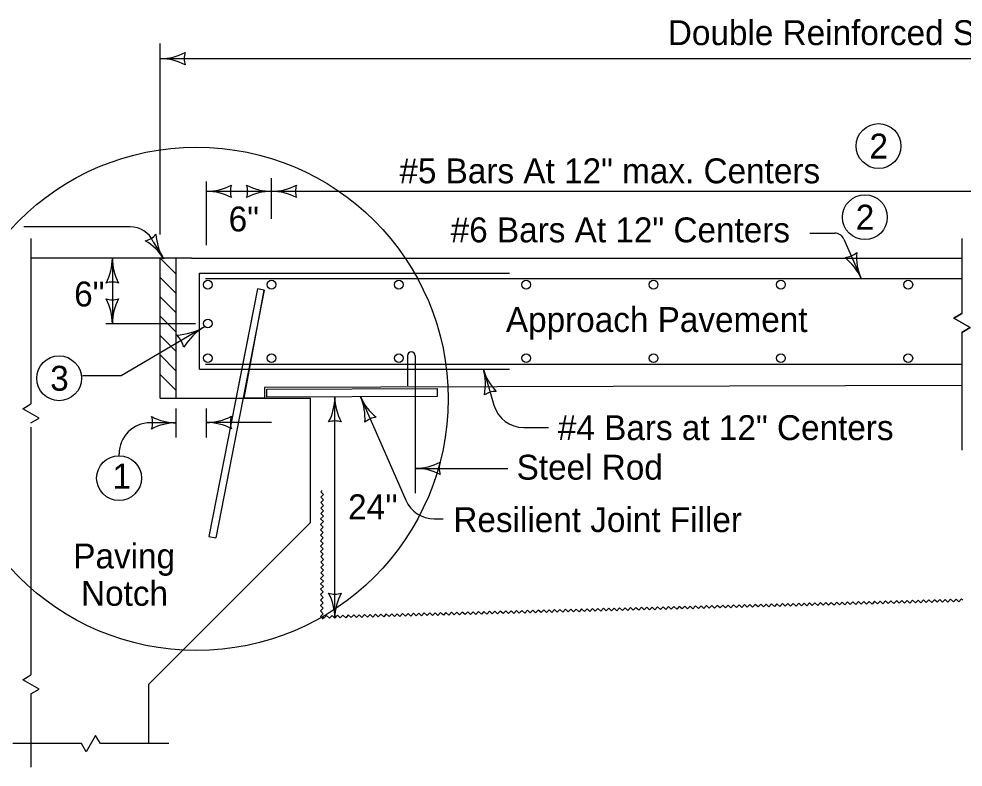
# Model space of a CAD drawing. Extents: x 8925 to 81668, y 4369 to 11918.
# Drawn here: x 10439 to 11198, y 11317 to 11918 of the extents above; entities that cross this region are included whole.
import ezdxf

# ---------------------------------------------------------------- set-up
doc = ezdxf.new("R2010")
doc.units = 0
for name, color, linetype in [('dsnShtPlotShapeBatchPrint', 7, 'Continuous'), ('dsnStdBorder', 7, 'Continuous'), ('Level 2', 7, 'Continuous'), ('Level 3', 7, 'Continuous')]:
    doc.layers.add(name, color=color, linetype=linetype)

msp = doc.modelspace()

# ---------------------------------------------------------------- linework, layer by layer
at = {"layer": 'dsnShtPlotShapeBatchPrint'}
for p, q in [((10552.7, 11779.04), (10552.7, 11897.97)), ((10552.7, 11885.92), (11924.35, 11885.92)), ((10642.06, 11757.38), (10642.06, 11789.95)), ((10589.84, 11736.03), (10589.84, 11787.22)), ((10552.7, 11744.67), (10552.7, 11779.04)), ((10642.06, 11779.35), (10589.84, 11779.35)), ((11212.31, 11779.35), (10642.06, 11779.35)), ((10528.55, 11750.92), (10443.13, 11750.92)), ((11074.65, 11745.77), (11094.51, 11745.77)), ((11101.92, 11740.93), (11115.71, 11709.42)), ((10514.2, 11725.71), (10514.2, 11673.05)), ((10565.57, 11613.18), (10565.57, 11725.71)), ((10565.57, 11613.18), (10565.57, 11725.71)), ((10577.7, 11725.71), (11196.67, 11725.71)), ((11196.67, 11725.71), (11196.67, 11681.27)), ((10630.73, 11701.11), (10591.71, 11502.08)), ((10636.29, 11700.02), (10597.26, 11500.99)), ((10630.73, 11701.11), (10613.41, 11612.76)), ((10620.09, 11613.18), (10636.29, 11700.02)), ((10636.29, 11700.02), (10630.73, 11701.11)), ((10636.29, 11700.02), (10630.73, 11701.11)), ((11196.67, 11681.27), (11190.1, 11677.49)), ((11190.1, 11677.49), (11203.23, 11669.89)), ((10581.11, 11673.05), (10509, 11673.05)), ((10588.33, 11670.58), (10521.42, 11631.21)), ((11203.23, 11669.89), (11196.67, 11666.11)), ((11196.67, 11666.11), (11196.67, 11623.41)), ((10812.25, 11636.46), (10820.69, 11607.62)), ((10521.42, 11631.21), (10490.23, 11631.21)), ((11196.67, 11623.41), (10636.5, 11621.92)), ((10636.5, 11621.92), (10636.5, 11613.18)), ((10636.5, 11621.91), (10636.5, 11613.18)), ((10638.22, 11620.45), (10775.14, 11620.96)), ((10775.14, 11620.96), (10775.16, 11614.48)), ((10613.41, 11612.76), (10565.57, 11613.18)), ((10636.5, 11613.18), (10620.09, 11613.18)), ((10638.25, 11613.98), (10638.22, 11620.45)), ((10775.16, 11614.48), (10638.25, 11613.98)), ((10692.98, 11436.67), (10692.98, 11614.18)), ((10713.64, 11614.25), (10749.94, 11531.33)), ((10565.57, 11581.77), (10565.57, 11605.08)), ((10589.84, 11581.62), (10589.84, 11604.93)), ((10565.77, 11593.49), (10544.6, 11593.49)), ((10642.06, 11593.76), (10589.84, 11593.76)), ((10844.68, 11589.65), (10864.46, 11589.65)), ((10519.6, 11567.08), (10519.6, 11568.49)), ((10757.52, 11556.9), (10831.85, 11556.9)), ((10772.84, 11516.36), (10780.05, 11516.36)), ((10591.71, 11502.08), (10597.26, 11500.99))]:
    msp.add_line(p, q, dxfattribs=at)
for points in [[(11196.67, 11681.27), (11190.1, 11677.49), (11203.24, 11669.89), (11196.67, 11666.11)], [(10682.7, 11539.17), (10681.61, 11538.09), (10683.78, 11535.9), (10681.59, 11533.72), (10683.77, 11531.54), (10681.58, 11529.36), (10683.75, 11527.18), (10681.56, 11525.01), (10683.74, 11522.82), (10681.56, 11520.64), (10683.72, 11518.46), (10681.54, 11516.28), (10683.7, 11514.1), (10681.52, 11511.93), (10683.69, 11509.74), (10681.51, 11507.56), (10683.68, 11505.38), (10681.49, 11503.2), (10683.66, 11501.01), (10681.48, 11498.84), (10683.65, 11496.66), (10681.47, 11494.48), (10683.63, 11492.29), (10681.45, 11490.12), (10683.62, 11487.94), (10682.53, 11486.85)], [(10682.7, 11487.1), (10681.61, 11486.02), (10683.78, 11483.83), (10681.59, 11481.66), (10683.77, 11479.47), (10681.58, 11477.29), (10683.75, 11475.11), (10681.56, 11472.94), (10683.74, 11470.75), (10681.55, 11468.57), (10683.72, 11466.39), (10681.54, 11464.22), (10683.7, 11462.03), (10681.52, 11459.86), (10683.69, 11457.67), (10681.5, 11455.49), (10683.68, 11453.31), (10681.49, 11451.13), (10683.66, 11448.95), (10681.48, 11446.77), (10683.65, 11444.59), (10681.47, 11442.41), (10683.63, 11440.22), (10681.45, 11438.05), (10683.62, 11435.87)], [(10988.23, 11445.5), (10987.11, 11446.56), (10984.98, 11444.33), (10982.75, 11446.45), (10980.63, 11444.21), (10978.39, 11446.33), (10976.27, 11444.1), (10974.03, 11446.22), (10971.91, 11443.99), (10969.67, 11446.11), (10967.55, 11443.88), (10965.31, 11445.99), (10963.19, 11443.76), (10960.96, 11445.88), (10958.83, 11443.64), (10956.6, 11445.77), (10954.47, 11443.53), (10952.23, 11445.65), (10950.11, 11443.42), (10947.87, 11445.54), (10945.75, 11443.3), (10943.52, 11445.42), (10941.4, 11443.19), (10939.16, 11445.31), (10937.04, 11443.08), (10935.92, 11444.14)], [(11040.53, 11446.87), (11039.41, 11447.93), (11037.29, 11445.69), (11035.06, 11447.81), (11032.94, 11445.58), (11030.7, 11447.7), (11028.57, 11445.47), (11026.34, 11447.59), (11024.21, 11445.35), (11021.97, 11447.47), (11019.85, 11445.24), (11017.62, 11447.36), (11015.5, 11445.13), (11013.26, 11447.25), (11011.14, 11445.01), (11008.9, 11447.13), (11006.78, 11444.9), (11004.54, 11447.02), (11002.42, 11444.78), (11000.18, 11446.9), (10998.06, 11444.67), (10995.82, 11446.79), (10993.7, 11444.55), (10991.47, 11446.68), (10989.34, 11444.44), (10988.23, 11445.5)], [(11092.84, 11448.24), (11091.72, 11449.29), (11089.6, 11447.06), (11087.36, 11449.18), (11085.24, 11446.95), (11083, 11449.06), (11080.88, 11446.83), (11078.64, 11448.95), (11076.52, 11446.72), (11074.28, 11448.84), (11072.16, 11446.61), (11069.92, 11448.73), (11067.81, 11446.49), (11065.57, 11448.61), (11063.44, 11446.38), (11061.21, 11448.5), (11059.09, 11446.27), (11056.85, 11448.39), (11054.72, 11446.15), (11052.49, 11448.27), (11050.37, 11446.03), (11048.13, 11448.15), (11046.01, 11445.92), (11043.77, 11448.04), (11041.65, 11445.81), (11040.53, 11446.87)], [(11145.15, 11449.6), (11144.03, 11450.66), (11141.91, 11448.43), (11139.67, 11450.54), (11137.55, 11448.31), (11135.31, 11450.43), (11133.18, 11448.2), (11130.95, 11450.32), (11128.83, 11448.09), (11126.59, 11450.2), (11124.47, 11447.97), (11122.23, 11450.09), (11120.11, 11447.86), (11117.87, 11449.98), (11115.75, 11447.75), (11113.51, 11449.87), (11111.39, 11447.63), (11109.16, 11449.75), (11107.04, 11447.52), (11104.8, 11449.64), (11102.67, 11447.4), (11100.44, 11449.52), (11098.31, 11447.29), (11096.08, 11449.41), (11093.96, 11447.17), (11092.84, 11448.24)], [(11197.45, 11450.97), (11196.34, 11452.02), (11194.21, 11449.79), (11191.98, 11451.91), (11189.85, 11449.68), (11187.61, 11451.8), (11185.49, 11449.57), (11183.26, 11451.68), (11181.14, 11449.45), (11178.9, 11451.57), (11176.77, 11449.34), (11174.54, 11451.46), (11172.42, 11449.23), (11170.18, 11451.34), (11168.06, 11449.11), (11165.82, 11451.23), (11163.7, 11449), (11161.46, 11451.11), (11159.34, 11448.89), (11157.1, 11451), (11154.98, 11448.77), (11152.75, 11450.89), (11150.62, 11448.65), (11148.38, 11450.77), (11146.26, 11448.54), (11145.15, 11449.6)], [(10726.7, 11438.67), (10725.58, 11439.73), (10723.45, 11437.5), (10721.22, 11439.62), (10719.09, 11437.38), (10716.86, 11439.5), (10714.74, 11437.27), (10712.5, 11439.39), (10710.38, 11437.16), (10708.14, 11439.28), (10706.02, 11437.04), (10703.78, 11439.16), (10701.66, 11436.93), (10699.42, 11439.05), (10697.3, 11436.82), (10695.06, 11438.94), (10692.94, 11436.7), (10690.71, 11438.82), (10688.58, 11436.59), (10686.34, 11438.71), (10684.22, 11436.48), (10683.16, 11437.48)], [(10779, 11440.04), (10777.88, 11441.1), (10775.76, 11438.86), (10773.52, 11440.98), (10771.4, 11438.75), (10769.16, 11440.87), (10767.04, 11438.64), (10764.81, 11440.76), (10762.68, 11438.52), (10760.45, 11440.64), (10758.32, 11438.41), (10756.09, 11440.53), (10753.97, 11438.3), (10751.73, 11440.42), (10749.61, 11438.18), (10747.37, 11440.3), (10745.25, 11438.07), (10743.01, 11440.19), (10740.89, 11437.95), (10738.65, 11440.08), (10736.53, 11437.84), (10734.3, 11439.96), (10732.17, 11437.72), (10729.93, 11439.85), (10727.81, 11437.61), (10726.7, 11438.67)], [(10831.31, 11441.41), (10830.19, 11442.46), (10828.07, 11440.23), (10825.83, 11442.35), (10823.71, 11440.12), (10821.47, 11442.23), (10819.35, 11440), (10817.11, 11442.12), (10814.99, 11439.89), (10812.75, 11442.01), (10810.63, 11439.78), (10808.4, 11441.89), (10806.27, 11439.66), (10804.04, 11441.78), (10801.91, 11439.55), (10799.67, 11441.67), (10797.56, 11439.43), (10795.32, 11441.55), (10793.19, 11439.32), (10790.96, 11441.44), (10788.83, 11439.21), (10786.6, 11441.33), (10784.48, 11439.09), (10782.24, 11441.21), (10780.12, 11438.98), (10779, 11440.04)], [(10883.62, 11442.77), (10882.5, 11443.83), (10880.37, 11441.6), (10878.14, 11443.71), (10876.01, 11441.48), (10873.77, 11443.6), (10871.66, 11441.37), (10869.42, 11443.49), (10867.29, 11441.26), (10865.06, 11443.37), (10862.93, 11441.14), (10860.7, 11443.26), (10858.58, 11441.03), (10856.35, 11443.15), (10854.22, 11440.92), (10851.98, 11443.03), (10849.86, 11440.8), (10847.62, 11442.92), (10845.5, 11440.69), (10843.26, 11442.8), (10841.14, 11440.57), (10838.91, 11442.69), (10836.79, 11440.46), (10834.55, 11442.58), (10832.43, 11440.34), (10831.31, 11441.41)], [(10935.92, 11444.14), (10934.8, 11445.19), (10932.68, 11442.96), (10930.45, 11445.08), (10928.32, 11442.85), (10926.08, 11444.97), (10923.96, 11442.74), (10921.72, 11444.85), (10919.6, 11442.62), (10917.36, 11444.74), (10915.24, 11442.51), (10913.01, 11444.63), (10910.88, 11442.4), (10908.65, 11444.51), (10906.53, 11442.28), (10904.29, 11444.4), (10902.17, 11442.17), (10899.93, 11444.29), (10897.81, 11442.05), (10895.57, 11444.17), (10893.45, 11441.94), (10891.21, 11444.06), (10889.09, 11441.82), (10886.85, 11443.94), (10884.73, 11441.71), (10883.62, 11442.77)]]:
    msp.add_lwpolyline(points, dxfattribs=at)
for centre, radius in [((10581.86, 11612.73), 202.08), ((10590.91, 11673.22), 3.55)]:
    msp.add_circle(centre, radius, dxfattribs=at)
for centre, radius in [((10528.55, 11730.72), 20.21), ((11094.51, 11737.69), 8.08)]:
    msp.add_arc(centre, radius, 23.64012, 90, dxfattribs=at)
at = {"layer": 'dsnStdBorder'}
for p, q in [((10448.81, 11741.35), (10448.81, 11702.2)), ((10547.06, 11738.82), (10555.39, 11725.19)), ((11196.67, 11741.35), (11196.67, 11681.27)), ((10577.7, 11725.71), (10448.81, 11725.71)), ((10552.7, 11613.18), (10552.7, 11725.71)), ((10565.57, 11712.84), (10552.7, 11725.71)), ((10577.7, 11725.71), (11196.67, 11725.71)), ((10584.28, 11713.62), (10833.14, 11713.62)), ((10584.28, 11636.46), (10584.28, 11713.62)), ((10565.57, 11697.29), (10552.7, 11710.16)), ((10588.91, 11709.42), (11196.67, 11709.42)), ((10448.81, 11702.2), (10448.81, 11608.61)), ((10565.57, 11681.73), (10552.7, 11694.6)), ((10565.57, 11666.17), (10552.7, 11679.04)), ((10565.57, 11650.62), (10552.7, 11663.49)), ((11196.67, 11666.11), (11196.67, 11571.49)), ((10565.57, 11635.06), (10552.7, 11647.93)), ((10584.28, 11636.46), (10833.14, 11636.46)), ((10588.91, 11640.46), (11196.67, 11640.46)), ((10565.57, 11619.51), (10552.7, 11632.38)), ((11196.67, 11623.41), (10636.5, 11621.92)), ((10638.22, 11620.45), (10775.14, 11620.96)), ((10775.14, 11620.96), (10775.16, 11614.48)), ((10552.7, 11613.18), (10673.43, 11613.18)), ((10638.25, 11613.98), (10638.22, 11620.45)), ((10775.16, 11614.48), (10638.25, 11613.98)), ((10673.43, 11513.56), (10673.43, 11613.18)), ((10448.81, 11590.07), (10448.81, 11390.98)), ((10543.59, 11383.73), (10673.43, 11513.56)), ((10543.59, 11335.88), (10543.59, 11383.73)), ((10448.81, 11375.82), (10448.81, 11317.01)), ((10489.43, 11335.88), (10434.36, 11335.88)), ((10559.65, 11335.88), (10504.59, 11335.88))]:
    msp.add_line(p, q, dxfattribs=at)
for points in [[(11196.67, 11666.11), (11203.24, 11669.89), (11190.1, 11677.49), (11196.67, 11681.27)], [(10448.81, 11593.45), (10455.37, 11597.23), (10442.24, 11604.82), (10448.81, 11608.6)], [(10448.81, 11375.82), (10455.37, 11379.6), (10442.24, 11387.2), (10448.81, 11390.98)], [(10504.59, 11335.87), (10500.8, 11342.44), (10493.21, 11329.31), (10489.43, 11335.87)]]:
    msp.add_lwpolyline(points, dxfattribs=at)
for centre, radius in [((11129.74, 11815.71), 18), ((11118.75, 11758.59), 18), ((10590.91, 11704.42), 3.55), ((10642.06, 11704.42), 3.55), ((10744.37, 11704.42), 3.55), ((10846.67, 11704.42), 3.55), ((10948.98, 11704.42), 3.55), ((11051.28, 11704.42), 3.55), ((11153.59, 11704.42), 3.55), ((10471.42, 11629.24), 18), ((10590.91, 11645.36), 3.55), ((10642.06, 11645.36), 3.55), ((10744.37, 11645.36), 3.55), ((10846.67, 11645.36), 3.55), ((10948.98, 11645.36), 3.55), ((11051.28, 11645.36), 3.55), ((11153.59, 11645.36), 3.55), ((10519.6, 11549.08), 18)]:
    msp.add_circle(centre, radius, dxfattribs=at)
for centre, radius, start, end in [((11101.04, 11742.93), 16.85, 275.90677, 311.37347), ((11155.68, 11726.91), 43.63, 175.56763, 203.64012), ((11075.74, 11691.92), 43.63, 23.64012, 51.71261), ((10563.78, 11712.28), 48.39, 272.40408, 300.47657), ((10612.87, 11628.88), 48.39, 120.47657, 148.54906), ((10553.36, 11650), 18.69, 12.74322, 48.20992), ((10844.68, 11614.65), 25, 196.32643, 270), ((10544.6, 11568.49), 25, 90, 180), ((10772.84, 11541.36), 25, 203.64012, 270), ((10692.98, 11472.3), 16.42, 252.26665, 287.73335), ((10650.48, 11436.67), 42.5, 360, 28.07249), ((10735.48, 11436.67), 42.5, 151.92751, 180)]:
    msp.add_arc(centre, radius, start, end, dxfattribs=at)
at = {"layer": 'Level 2'}
for p, q in [((10751.23, 11647.3), (10751.23, 11623.15)), ((10757.52, 11647.3), (10757.52, 11537.08))]:
    msp.add_line(p, q, dxfattribs=at)
msp.add_arc((10754.37, 11647.3), 3.15, 0, 180, dxfattribs=at)
at = {"layer": 'Level 3'}
for centre, radius, start, end in [((10552.7, 11928.42), 42.5, 270, 298.07249), ((10588.34, 11885.92), 16.42, 162.26665, 197.73335), ((10552.7, 11843.42), 42.5, 61.92751, 90), ((10589.84, 11821.85), 42.5, 270, 298.07249), ((10625.48, 11779.35), 16.42, 162.26665, 197.73335), ((10606.43, 11779.35), 16.42, 342.26665, 17.73335), ((10642.06, 11821.85), 42.5, 241.92751, 270), ((10642.06, 11821.85), 42.5, 270, 298.07249), ((10677.7, 11779.35), 16.42, 162.26665, 197.73335), ((10589.84, 11736.85), 42.5, 61.92751, 90), ((10642.06, 11736.85), 42.5, 90, 118.07249), ((10642.06, 11736.85), 42.5, 61.92751, 90), ((10536.8, 11755.6), 16.42, 283.71154, 319.17824), ((10591.65, 11747.37), 42.5, 183.3724, 211.44489), ((10519.13, 11703.02), 42.5, 31.44489, 59.51738), ((10471.7, 11725.71), 42.5, 331.92751, 360), ((10556.7, 11725.71), 42.5, 180, 208.07249), ((10514.2, 11690.08), 16.42, 72.26665, 107.73335), ((10514.2, 11708.69), 16.42, 252.26665, 287.73335), ((10471.7, 11673.05), 42.5, 360, 28.07249), ((10556.7, 11673.05), 42.5, 151.92751, 180), ((10853.03, 11648.4), 42.5, 196.32643, 224.39892), ((10771.46, 11624.51), 42.5, 348.25394, 16.32643), ((10650.48, 11614.18), 42.5, 331.92751, 360), ((10735.48, 11614.18), 42.5, 180, 208.07249), ((10752.58, 11631.29), 42.5, 203.64012, 231.71261), ((10674.71, 11597.21), 42.5, 355.56763, 23.64012), ((10822.26, 11602.26), 16.42, 88.59307, 124.05978), ((10530.13, 11593.49), 16.42, 342.26665, 17.73335), ((10565.77, 11635.99), 42.5, 241.92751, 270), ((10589.84, 11636.26), 42.5, 270, 298.07249), ((10625.48, 11593.76), 16.42, 162.26665, 197.73335), ((10565.77, 11550.99), 42.5, 90, 118.07249), ((10589.84, 11551.26), 42.5, 61.92751, 90), ((10692.98, 11578.54), 16.42, 72.26665, 107.73335), ((10727.93, 11581.61), 16.42, 95.90677, 131.37347), ((10757.52, 11599.4), 42.5, 270, 298.07249), ((10793.16, 11556.9), 16.42, 162.26665, 197.73335), ((10757.52, 11514.4), 42.5, 61.92751, 90)]:
    msp.add_arc(centre, radius, start, end, dxfattribs=at)

# ---------------------------------------------------------------- texts
at = {"layer": 'dsnShtPlotShapeBatchPrint'}
for s, p in [('Double Reinforced Section (20\'-0" min.)', (10960.47, 11896.75)), ('2', (11122.41, 11805.71)), ('#5 Bars At 12" max. Centers', (10744.78, 11785.81)), ('6"', (10607.62, 11747.14)), ('2', (11111.42, 11748.59)), ('#6 Bars At 12" Centers', (10785.99, 11738.4)), ('6"', (10483.55, 11686.92)), ('Approach Pavement', (10830.36, 11666.37)), ('3', (10464.28, 11619.24)), ('#4 Bars at 12" Centers', (10872.12, 11579.59)), ('Steel Rod', (10838.97, 11547.82)), ('1', (10514.36, 11540.69)), ("24''", (10703.59, 11516.04)), ('Resilient Joint Filler', (10788.15, 11505.73)), ('Paving', (10482.82, 11476.54)), ('Notch', (10489.06, 11446.54))]:
    msp.add_text(s, height=20, dxfattribs=at).set_placement(p)

doc.saveas('drawing.dxf')
